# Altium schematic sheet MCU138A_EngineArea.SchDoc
size 431 x 279 mm; Date: Not shown in title block; ApprovedBy: Not shown in title block; CheckedBy: Not shown in title block; Author: Not shown in title block; CompanyName: Not shown in title block; DrawnBy: Jonathan Cohen; Engineer: Not shown in title block; Organization: Not shown in title block; Address1: Not shown in title block; Address2: Not shown in title block; Address3: Not shown in title block; Address4: Not shown in title block; DocumentNumber: 2; Revision: Use project parameter SCH_Rev; SheetNumber: 1; SheetTotal: 2; PageSetup: Record=PageOptions¦CenterHorizontal=True¦CenterVertical=True¦PrintScale=1.00¦XCorrection=1.00¦YCorrection=1.00¦PrintKind=0¦BorderSize=5000000¦LeftOffset=0¦BottomOffset=0¦Orientation=2¦PaperLength=1000¦PaperWidth=1000¦Scale=100¦PaperSource=15¦PrintQuality=600¦MediaType=1¦DitherType=10¦PaperKind=Letter¦PrintScaleMode=1
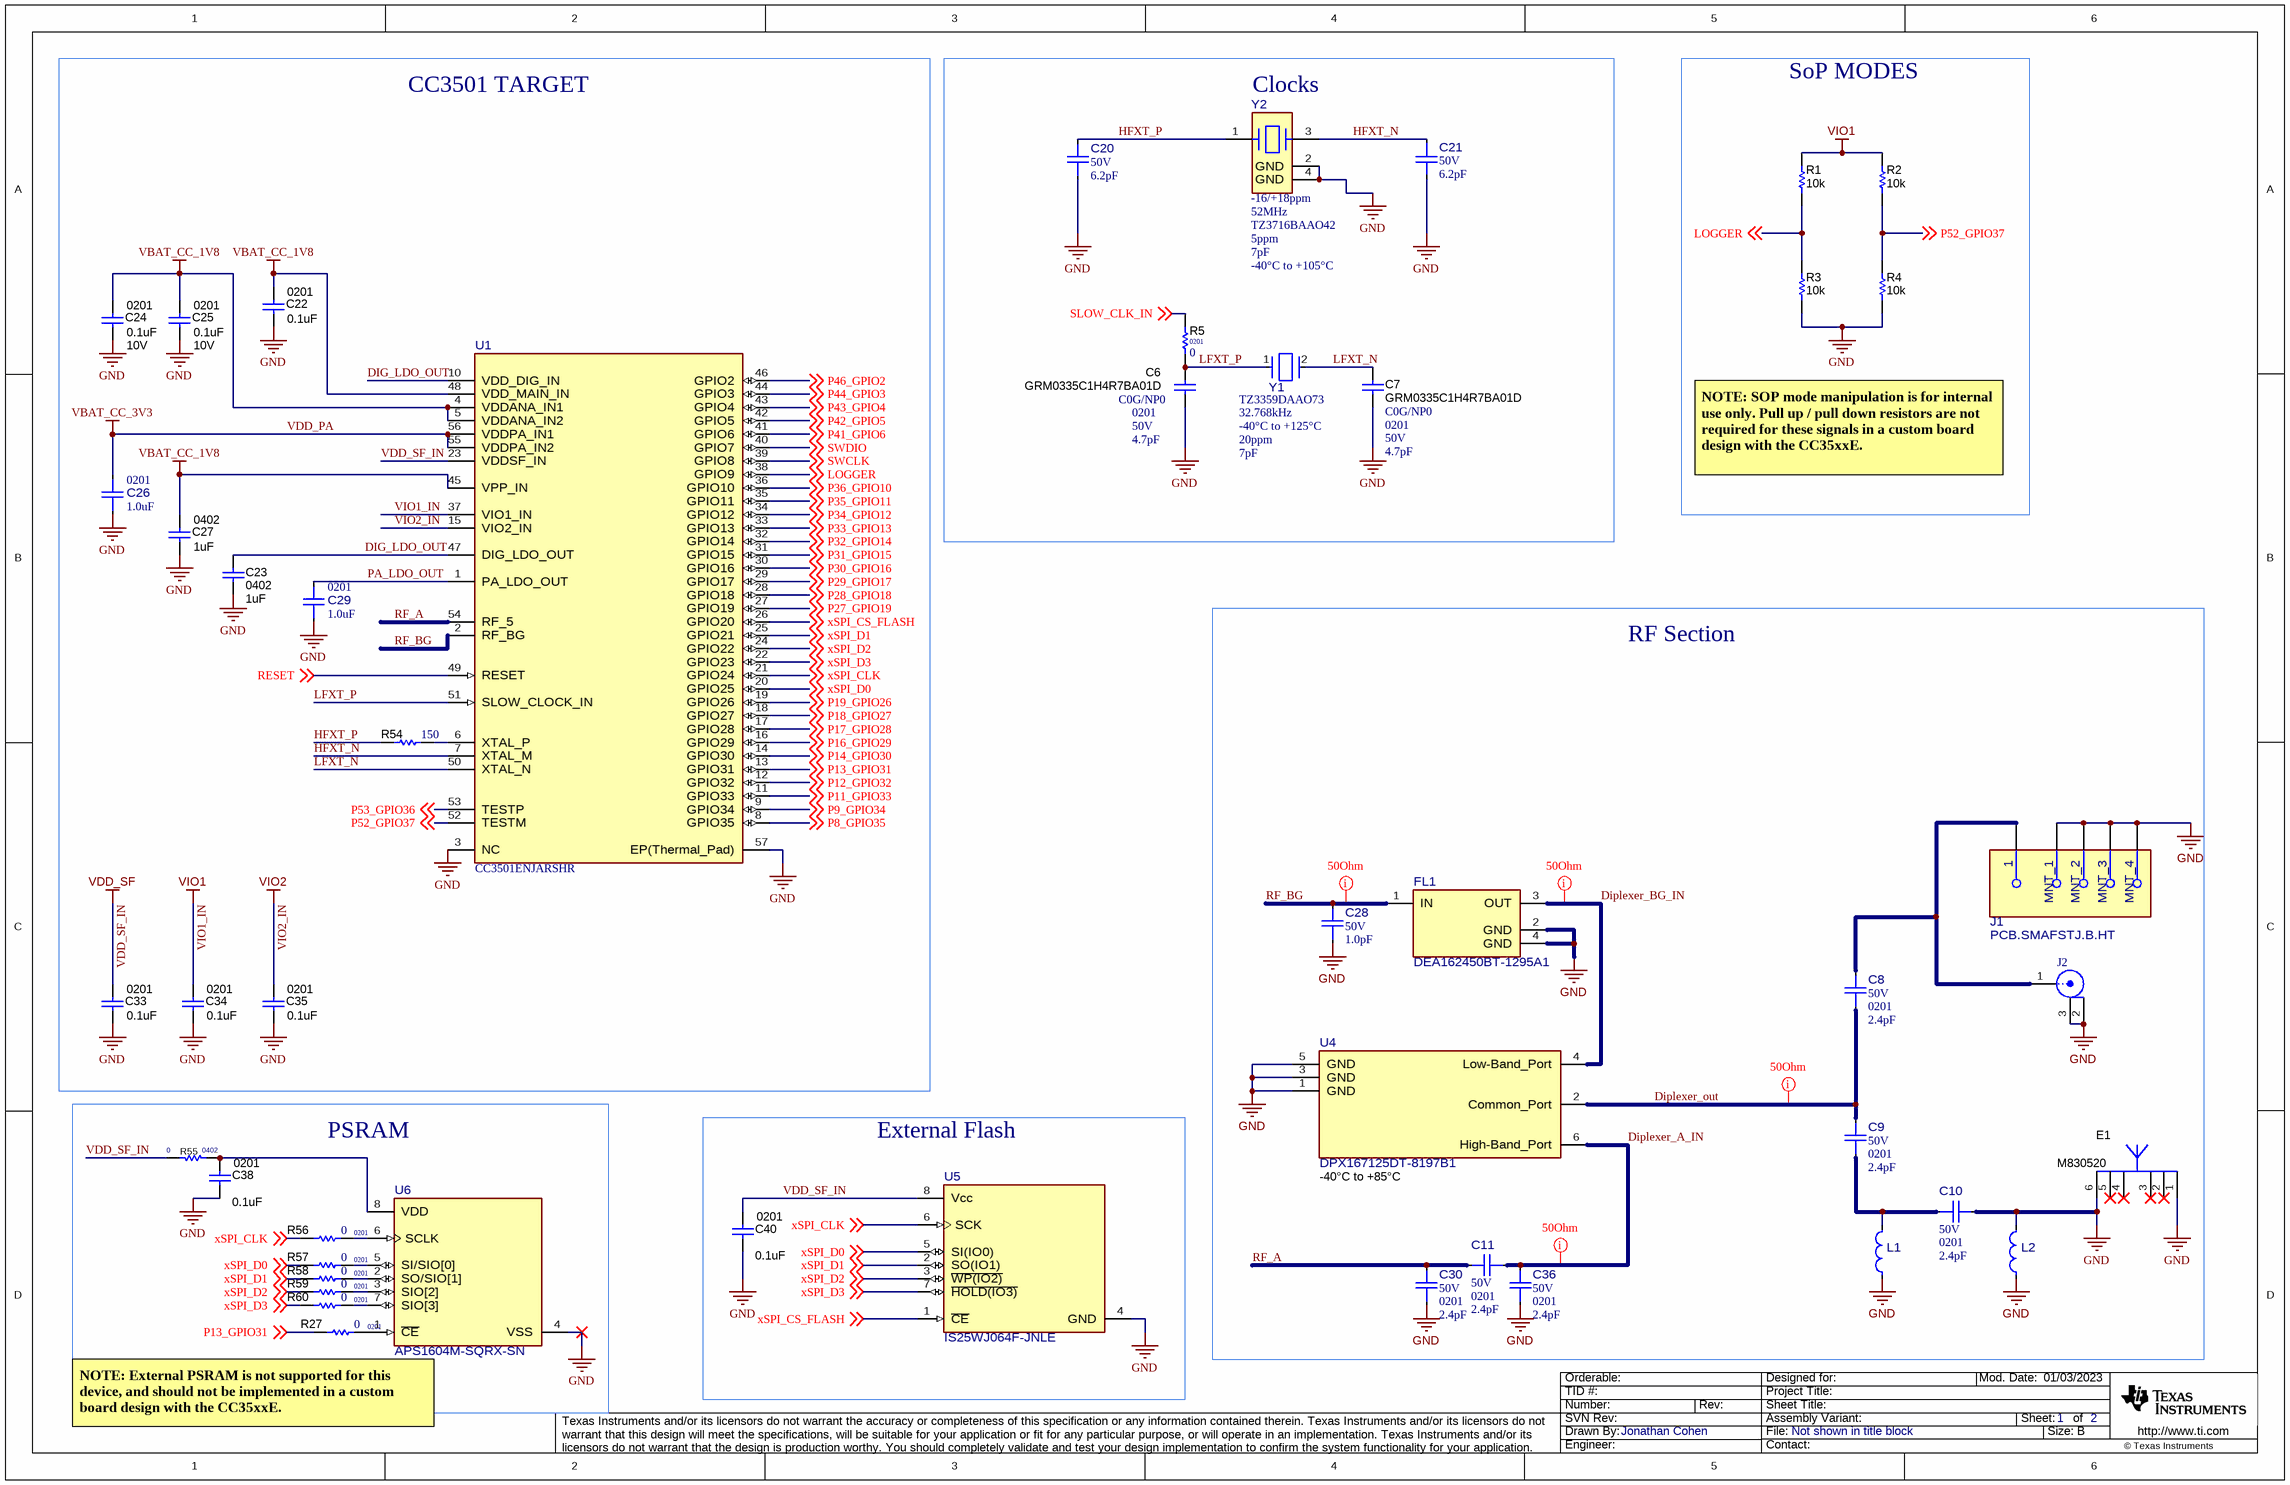
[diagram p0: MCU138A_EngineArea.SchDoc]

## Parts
C6  GRM0335C1H4R7BA01D  TempCo: C0G/NP0  PackageReference: 0201  VDC_V: 50V  ValueDisplayed: 4.7pF  [0201_033]
C7  GRM0335C1H4R7BA01D  TempCo: C0G/NP0  PackageReference: 0201  VDC_V: 50V  ValueDisplayed: 4.7pF  [0201_033]
C8  VDC_V: 50V  PackageReference: 0201  ValueDisplayed: 2.4pF  [FP-GRM0335C1H2R4BA01D_0201-MFG]  (hidden comment: GRM0335C1H2R4BA01D)
C9  VDC_V: 50V  PackageReference: 0201  ValueDisplayed: 2.4pF  [FP-GRM0335C1H2R4BA01D_0201-MFG]  (hidden comment: GRM0335C1H2R4BA01D)
C10  VDC_V: 50V  PackageReference: 0201  ValueDisplayed: 2.4pF  [FP-GRM0335C1H2R4BA01D_0201-MFG]  (hidden comment: GRM0335C1H2R4BA01D)
C11  VDC_V: 50V  PackageReference: 0201  ValueDisplayed: 2.4pF  [FP-GRM0335C1H2R4BA01D_0201-MFG]  (hidden comment: GRM0335C1H2R4BA01D)
C20  VDC_V: 50V  ValueDisplayed: 6.2pF  [FP-GRM0335C1H6R2BA01D_0201-MFG]  (hidden comment: GRM0335C1H6R2BA01D)
C21  VDC_V: 50V  ValueDisplayed: 6.2pF  [FP-GRM0335C1H6R2BA01D_0201-MFG]  (hidden comment: GRM0335C1H6R2BA01D)
C22  ValueDisplayed: 0.1uF  [0201]  (hidden comment: GRM033C71A104KE14D)
C23  ValueDisplayed: 1uF  [0402]  (hidden comment: GRM155R70J105MA12D)
C24  VDC_V: 10V  ValueDisplayed: 0.1uF  [0201]  (hidden comment: GRM033C71A104KE14D)
C25  VDC_V: 10V  ValueDisplayed: 0.1uF  [0201]  (hidden comment: GRM033C71A104KE14D)
C26  ValueDisplayed: 1.0uF  PackageReference: 0201  [FP-GRM033D70J105ME01D_0201-MFG]  (hidden comment: GRM033D70J105ME01D)
C27  ValueDisplayed: 1uF  [0402]  (hidden comment: GRM155R70J105MA12D)
C28  VDC_V: 50V  ValueDisplayed: 1.0pF  [FP-GRM0335C1H1R0CA01D_0201-MFG]  (hidden comment: GRM0335C1H1R0CA01D)
C29  ValueDisplayed: 1.0uF  PackageReference: 0201  [FP-GRM033D70J105ME01D_0201-MFG]  (hidden comment: GRM033D70J105ME01D)
C30  VDC_V: 50V  PackageReference: 0201  ValueDisplayed: 2.4pF  [FP-GRM0335C1H2R4BA01D_0201-MFG]  (hidden comment: GRM0335C1H2R4BA01D)
C33  ValueDisplayed: 0.1uF  [0201]  (hidden comment: GRM033C71A104KE14D)
C34  ValueDisplayed: 0.1uF  [0201]  (hidden comment: GRM033C71A104KE14D)
C35  ValueDisplayed: 0.1uF  [0201]  (hidden comment: GRM033C71A104KE14D)
C36  VDC_V: 50V  PackageReference: 0201  ValueDisplayed: 2.4pF  [FP-GRM0335C1H2R4BA01D_0201-MFG]  (hidden comment: GRM0335C1H2R4BA01D)
C38  ValueDisplayed: 0.1uF  [0201]  (hidden comment: GRM033C71A104KE14D)
C40  ValueDisplayed: 0.1uF  [0201]  (hidden comment: GRM033C71A104KE14D)
E1  M830520  [Ethertronics_M830520]
FL1  DEA162450BT-1295A1  [FP-DEA162450BT-1295A1_SMT_FILTER_1MM60_0MM80-MFG]
J1  PCB.SMAFSTJ.B.HT  [FP-PCB.SMAFSTJ.B.HT_SMT_SMA_JACK-MFG]
J2  U.FL-R-SMT-1(01)  [CONN_UFL-R-SMT-1]  (value not drawn)
L1  LQP03HQ3N9B02D  [FP-LQP03HQ3N9B02D_0201-MFG]  (value not drawn)
L2  LQP03HQ3N9B02D  [FP-LQP03HQ3N9B02D_0201-MFG]  (value not drawn)
R1  ValueDisplayed: 10k  [0402]  (hidden comment: RC0402FR-0710KL)
R2  ValueDisplayed: 10k  [0402]  (hidden comment: RC0402FR-0710KL)
R3  ValueDisplayed: 10k  [0402]  (hidden comment: RC0402FR-0710KL)
R4  ValueDisplayed: 10k  [0402]  (hidden comment: RC0402FR-0710KL)
R5  ValueDisplayed: 0  [0201]  (hidden comment: CRCW02010000Z0ED)
R27  ValueDisplayed: 0  [0201]  (hidden comment: CRCW02010000Z0ED)
R54  ValueDisplayed: 150  [0201]  (hidden comment: RC0201FR-7D150RL)
R55  ValueDisplayed: 0  [0402]  (hidden comment: CRCW04020000Z0ED)
R56  ValueDisplayed: 0  [0201]  (hidden comment: CRCW02010000Z0ED)
R57  ValueDisplayed: 0  [0201]  (hidden comment: CRCW02010000Z0ED)
R58  ValueDisplayed: 0  [0201]  (hidden comment: CRCW02010000Z0ED)
R59  ValueDisplayed: 0  [0201]  (hidden comment: CRCW02010000Z0ED)
R60  ValueDisplayed: 0  [0201]  (hidden comment: CRCW02010000Z0ED)
U1  CC3501ENJARSHR  [RSH0056D-MFG]
U4  DPX167125DT-8197B1  Operating Temperature Range: -40°C to +85°C  [FP-DPX167125DT-8197B1_SMD6-MFG]
U5  IS25WJ064F-JNLE  [FP-IS25WJ032F-JNLE_SOIC8-IPC_C]
U6  APS1604M-SQRX-SN  [FP-APS1604M-SQRX-SN_SOP8-IPC_C]
Y1  Frequency_Fixed: 32.768kHz  Load Capacitance: 7pF  Operating Temperature Range: -40°C to +125°C  Tolerance_%: 20ppm  [FP-TZ3359DAAO73_SMT2_1MM65_1MM05-MFG]  (hidden comment: TZ3359DAAO73)
Y2  Frequency Stability: -16/+18ppm  Frequency_Fixed: 52MHz  Frequency Tolerance: 5ppm  Load Capacitance: 7pF  Operating Temperature Range: -40°C to +105°C  [FP-TZ3716BAAO42_SMT_XTAL_2MM05_1MM65-MFG]  (hidden comment: TZ3716BAAO42)

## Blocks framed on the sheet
CC3501 TARGET: C22-C27 C29 C33-C35 R54 U1
Clocks: C6 C7 C20 C21 R5 Y1 Y2
SoP MODES: R1-R4
RF Section: C8-C11 C28 C30 C36 E1 FL1 J1 J2 L1 L2 U4
PSRAM: C38 R27 R55-R60 U6
External Flash: C40 U5

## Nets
GND: C6.2 C7.2 C10.2 C20.1 C21.2 C22.2 C23.1 C24.2 C25.2 C26.1 C27.2 C28.1 C29.1 C30.1 C33.2 C34.2 C35.2 C36.1 C38.2 C40.2 E1.1(Feed) E1.6 FL1.2(GND) FL1.4(GND) J1.2(MNT_1) J1.3(MNT_2) J1.4(MNT_3) J1.5(MNT_4) J2.2 J2.3 L1.1 L2.1 L2.2 R3.2 R4.2 U1.3(NC) U1.57(EP(Thermal_Pad)) U4.1(GND) U4.3(GND) U4.5(GND) U5.4(GND) U6.4(VSS) Y2.2(GND) Y2.4(GND)
VBAT_CC_1V8: C22.1 C24.1 C25.1 C27.1 U1.4(VDDANA_IN1) U1.5(VDDANA_IN2) U1.45(VPP_IN) U1.48(VDD_MAIN_IN)
VDD_PA: C26.2 U1.55(VDDPA_IN2) U1.56(VDDPA_IN1)  [also labelled VBAT_CC_3V3]
VDD_SF_IN: C33.1 C40.1 R55.2 U1.23(VDDSF_IN) U5.8(Vcc)  [also labelled VDD_SF]
VIO1_IN: C34.1 R1.1 R2.1 U1.37(VIO1_IN)  [also labelled VIO1]
VIO2_IN: C35.1 U1.15(VIO2_IN)  [also labelled VIO2]
DIG_LDO_OUT: C23.2 U1.10(VDD_DIG_IN) U1.47(DIG_LDO_OUT)
Diplexer_A_IN: C11.1 C36.2 U4.6(High-Band_Port)
Diplexer_BG_IN: FL1.3(OUT) U4.4(Low-Band_Port)
Diplexer_out: C8.1 C9.2 U4.2(Common_Port)
HFXT_N: C21.1 U1.7(XTAL_M) Y2.3(2_IN/OUT)
HFXT_P: C20.2 R54.2 Y2.1(1_IN/OUT)
LFXT_N: C7.1 U1.50(XTAL_N) Y1.2
LFXT_P: C6.1 R5.1 U1.51(SLOW_CLOCK_IN) Y1.1
LOGGER: R1.2 R3.1 U1.38(GPIO9) ; off-sheet LOGGER
P8_GPIO35: U1.8(GPIO35) ; off-sheet P8_GPIO35
P9_GPIO34: U1.9(GPIO34) ; off-sheet P9_GPIO34
P11_GPIO33: U1.11(GPIO33) ; off-sheet P11_GPIO33
P12_GPIO32: U1.12(GPIO32) ; off-sheet P12_GPIO32
P13_GPIO31: R27.1 U1.13(GPIO31) ; off-sheet P13_GPIO31
P14_GPIO30: U1.14(GPIO30) ; off-sheet P14_GPIO30
P16_GPIO29: U1.16(GPIO29) ; off-sheet P16_GPIO29
P17_GPIO28: U1.17(GPIO28) ; off-sheet P17_GPIO28
P18_GPIO27: U1.18(GPIO27) ; off-sheet P18_GPIO27
P19_GPIO26: U1.19(GPIO26) ; off-sheet P19_GPIO26
P27_GPIO19: U1.27(GPIO19) ; off-sheet P27_GPIO19
P28_GPIO18: U1.28(GPIO18) ; off-sheet P28_GPIO18
P29_GPIO17: U1.29(GPIO17) ; off-sheet P29_GPIO17
P30_GPIO16: U1.30(GPIO16) ; off-sheet P30_GPIO16
P31_GPIO15: U1.31(GPIO15) ; off-sheet P31_GPIO15
P32_GPIO14: U1.32(GPIO14) ; off-sheet P32_GPIO14
P33_GPIO13: U1.33(GPIO13) ; off-sheet P33_GPIO13
P34_GPIO12: U1.34(GPIO12) ; off-sheet P34_GPIO12
P35_GPIO11: U1.35(GPIO11) ; off-sheet P35_GPIO11
P36_GPIO10: U1.36(GPIO10) ; off-sheet P36_GPIO10
P41_GPIO6: U1.41(GPIO6) ; off-sheet P41_GPIO6
P42_GPIO5: U1.42(GPIO5) ; off-sheet P42_GPIO5
P43_GPIO4: U1.43(GPIO4) ; off-sheet P43_GPIO4
P44_GPIO3: U1.44(GPIO3) ; off-sheet P44_GPIO3
P46_GPIO2: U1.46(GPIO2) ; off-sheet P46_GPIO2
P52_GPIO37: R2.2 R4.1 U1.52(TESTM) ; off-sheet P52_GPIO37
P53_GPIO36: U1.53(TESTP) ; off-sheet P53_GPIO36
PA_LDO_OUT: C29.2 U1.1(PA_LDO_OUT)
RESET: U1.49(RESET) ; off-sheet RESET
RF_A: C11.2 C30.2 U1.54(RF_5)
RF_BG: C28.2 FL1.1(IN) U1.2(RF_BG)
SLOW_CLK_IN: R5.2 ; off-sheet SLOW_CLK_IN
SWCLK: U1.39(GPIO8) ; off-sheet SWCLK
SWDIO: U1.40(GPIO7) ; off-sheet SWDIO
xSPI_CLK: R56.1 U1.21(GPIO24) U5.6(SCK) ; off-sheet xSPI_CLK
xSPI_CS_FLASH: U1.26(GPIO20) U5.1(~{CE}) ; off-sheet xSPI_CS_FLASH
xSPI_D0: R57.1 U1.20(GPIO25) U5.5(SI(IO0)) ; off-sheet xSPI_D0
xSPI_D1: R58.1 U1.25(GPIO21) U5.2(SO(IO1)) ; off-sheet xSPI_D1
xSPI_D2: R59.1 U1.24(GPIO22) U5.3(~{WP(IO2)}) ; off-sheet xSPI_D2
xSPI_D3: R60.1 U1.22(GPIO23) U5.7(~{HOLD(IO3)}) ; off-sheet xSPI_D3
NetC8_2: C8.2 J1.1 J2.1
NetC9_1: C9.1 C10.1 L1.2
NetC38_1: C38.1 R55.1 U6.8(VDD)
NetR27_2: R27.2 U6.1(~{CE})
NetR54_1: R54.1 U1.6(XTAL_P)
NetR56_2: R56.2 U6.6(SCLK)
NetR57_2: R57.2 U6.5(SI/SIO[0])
NetR58_2: R58.2 U6.2(SO/SIO[1])
NetR59_2: R59.2 U6.3(SIO[2])
NetR60_2: R60.2 U6.7(SIO[3])

Not connected (* = marked no-connect by the designer): E1 2(GND)* 3(GND)* 4(Feed)* 5*

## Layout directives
rule Undefined: Diplexer_A_IN, Diplexer_BG_IN, Diplexer_out, RF_BG

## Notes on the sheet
- NOTE: SOP mode manipulation is for internal use only. Pull up / pull down resistors are not required for these signals in a custom board design with the CC35xxE.
- NOTE: External PSRAM is not supported for this device, and should not be implemented in a custom board design with the CC35xxE.

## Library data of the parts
C6 C7 = CMP-0080076-1: CAP, CERM, 4.7 pF, 50 V,+/- 3%, C0G/NP0, 0201; Manufacturer: MuRata; TaMin_C: -55°C; Polarized: N; SizeAreaWB_mm2: 2.08; U/M: EA; Value: 4.7pF; TaMax_C: 125°C; SizeZ_mm: 0.33; SizeX_mm: 0.6; SizeY_mm: 0.3; SizeArea_mm2: 0.18; AEC Category: Q200
C8-C11 C30 C36 = CMP-0091210-1: Chip Multilayer Ceramic Capacitors for General Purpose, 0201, 2.4pF, C0G, 30ppm/°C, 0.1pF, 50V; Manufacturer: Murata; SizeZ_mm: 0.33mm; AEC Qualified: No
C20 C21 = CMP-0096092-1: Chip Multilayer Ceramic Capacitors for General Purpose, 0201, 6.2pF, C0G, 30ppm/°C, 0.1pF, 50V; Manufacturer: Murata; SizeZ_mm: 0.33mm; AEC Qualified: No; Tolerance_%: 1.6%
C22 C33 C34 C38 C40 = CMP-0064969-1: CAP, CERM, 0.1 uF, 10 V,+/- 10%, X7S, 0201; Manufacturer: MuRata; TaMin_C: -55°C; Polarized: N; SizeAreaWB_mm2: 2.08; Value1: Unknown; U/M: EA; Value: 0.1uF; TaMax_C: 125°C; SizeZ_mm: 0.26; SizeX_mm: 0.6; SizeY_mm: 0.3; Value2: 10V; SizeArea_mm2: 0.18; Cap_F: 100nF; AEC Category: Q200
C23 C27 = CMP-0006624-2: CAP, CERM, 1 uF, 6.3 V, +/- 20%, X7R, 0402; Manufacturer: MuRata; TaMin_C: -55°C; Polarized: N; SizeAreaWB_mm2: 3; Value1: Unknown; U/M: EA; Value: 1uF; TaMax_C: 125°C; SizeZ_mm: 0.6; SizeX_mm: 1; SizeY_mm: 0.5; Value2: 6.3V; Cap_F: 1µF; AEC Category: Q200
C24 C25 = CMP-0064969-1: CAP, CERM, 0.1 uF, 10 V,+/- 10%, X7S, 0201; Manufacturer: MuRata; TaMin_C: -55°C; Polarized: N; SizeAreaWB_mm2: 2.08; Value1: Unknown; U/M: EA; Value: 0.1uF; TaMax_C: 125°C; SizeZ_mm: 0.26; SizeX_mm: 0.6; SizeY_mm: 0.3; SizeArea_mm2: 0.18; Cap_F: 100nF; AEC Category: Q200
C26 C29 = CMP-0095016-1: Chip Multilayer Ceramic Capacitors for General Purpose, 0201, 1.0uF, X7T, +22%/-33%, 20%, 6.3V; Manufacturer: Murata; Cap_F: 1µF; AEC Qualified: No; Value: 1µF; SizeZ_mm: 0.39mm
C28 = CMP-0090893-1: Chip Multilayer Ceramic Capacitors for General Purpose, 0201, 1.0pF, C0G, 30ppm/°C, 0.25pF, 50V; Manufacturer: Murata; Value: 1pF; SizeZ_mm: 0.33mm; AEC Qualified: No
C35 = CMP-0064969-1: CAP, CERM, 0.1 uF, 10 V,+/- 10%, X7S, 0201; Manufacturer: MuRata; TaMin_C: -55°C; Polarized: N; SizeAreaWB_mm2: 2.08; Value1: Unknown; U/M: EA; TaMax_C: 125°C; SizeZ_mm: 0.26; SizeX_mm: 0.6; SizeY_mm: 0.3; Value2: 10V; SizeArea_mm2: 0.18; Cap_F: 100nF; AEC Category: Q200
E1 = CMP-0001857-1: WLAN ANTENNA 802.11, SMD; Manufacturer: Ethertronics; Alternate Manufacturer: ----; SizeAreaWB_mm2: 50; SizeArea_mm2: 24; SizeX_mm: 3; SizeY_mm: 8; SizeZ_mm: 1.33
FL1 = CMP-0091509-1: 2.45GHz Center Frequency Band Pass RF Filter (Radio Frequency) 100MHz Bandwidth 1.8dB 0603 (1608 Metric), 3 PC Pad; Manufacturer: TDK; Bandwidth: 2400-2500MHz; AEC Qualified: No; Insertion Loss: 1.95dB; SizeZ_mm: 0.7mm
J1 = CMP-0089646-1: SMA Connector Jack, Female Socket 50Ohm Surface Mount Solder; Manufacturer: Taoglas Limited; SizeZ_mm: 10.7mm; AEC Qualified: No; ContactFinish: Gold; Frequency_Fixed: 0-12.4GHz; Voltage_V: 335V; Conn Orientation: Straight; Shrouded: true; Impedance: 50Ω; Standoff Height: 0.7mm; Dielectric Material: PTFE; Is Female: yes
J2 = CMP-0075320-1: Receptacle, Ultra Miniature Coaxial, Male Pin, 50 ohm, SMT; Manufacturer: Hirose Electric Co. Ltd.; Alternate Manufacturer: ----; CNHeader: False; Gender: Female; ContactFinish: Gold
L1 L2 = CMP-0090712-1: 3.9nH Unshielded Thick Film Inductor 500mA 170mOhm Max 0201 (0603 Metric); Manufacturer: Murata; Tolerance_%: 0.1nH; Test Frequency: 500MHz; Material: Non-Magnetic; TaMin_C: -55°C; SizeZ_mm: 0.42mm; TaMax_C: +125°C; AEC Qualified: No; DCR_ohm: 0.17; Q Factor: 20; Self Resonant Frequency: 7GHz
R1-R4 = CMP-0078669-1: RES, 10.0 k, 1%, 0.063 W, 0402; Manufacturer: Yageo America; Power_W: 63mW; Green_Lifecycle: Active; TempCo: 100 ppm/C; Value_Code: 10k0; Green_REACh: Passed; Value: 10.0k; EIA_Code: E96; SizeX_mm: 1; SizeY_mm: 0.5; SizeZ_mm: 0.6; Value2: 0.063W; AEC Qualified: N; AEC Category: Q200
R5 R27 R56-R60 = CMP-0027008-4: RES, 0, 5%, 0.05 W, 0201; Manufacturer: Vishay-Dale; Power_W: 50mW; TempCo: ppm/C; Value_Code: 0000; Value: 0; EIA_Code: E24; SizeX_mm: 0.6; SizeY_mm: 0.3; SizeZ_mm: 0.26; Value2: 0.05W; SizeArea_mm2: 0.18; AEC Qualified: N; AEC Category: Q200
R54 = CMP-0027960-1: RES, 150, 1%, 0.05 W, 0201; Manufacturer: Yageo America; Power_W: 50mW; TempCo: 200 ppm/C; Value_Code: 150R; U/M: EA; Value: 150; EIA_Code: E96; SizeX_mm: 0.6; SizeY_mm: 0.3; SizeZ_mm: 0.26; Value2: 0.05W; SizeArea_mm2: 0.18; AEC Qualified: N; VDC_V: 25V; AEC Category: Q200
R55 = CMP-0026822-3: RES, 0, 5%, 0.063 W, AEC-Q200 Grade 0, 0402; Manufacturer: Vishay-Dale; Power_W: 63mW; TempCo: 200 ppm/C; Value_Code: 0000; Value: 0; EIA_Code: E24; SizeX_mm: 1; SizeY_mm: 0.5; SizeZ_mm: 0.6; Value2: 0.063W; AEC Qualified: Y; VDC_V: 50V; AEC Category: Q200
U1 = CMP-0121078-1: Manufacturer: Texas Instruments; SizeZ_mm: 1mm; Standoff Height: 0mm
U4 = CMP-0091972-1: Multilayer Diplexer For 2.4-2.5GHz W-LAN & Bluetooth / 5-7GHz W-LAN; Manufacturer: TDK; Insertion Loss: 1dB; SizeZ_mm: 0.7mm; AEC Qualified: No
U5 = CMP-0120365-1: FLASH - NOR Memory IC 64Mbit SPI - Quad I/O, QPI, DTR 133 MHz 6 ns 8-SOP; Manufacturer: ISSI; Part Number: IS25WJ032F-JNLE; SizeZ_mm: 1.75mm; Access Time: 7ns; Frequency_Fixed: 133MHz; Max Supply Voltage: 2V; Memory Size: 32Mbits; Min Supply Voltage: 1.65V; Nominal Supply Current: 1.2-10mA; Standoff Height: 0.1mm
U6 = CMP-0121002-1: DRAM IoT RAM 16Mb QSPI (x1,x4) SDR 144/84MHz, RBX, 1.8V, Ext. Temp., SOP8; Manufacturer: AP Memory; SizeZ_mm: 1.75mm; Access Time: 5.5ns; AEC Qualified: No; Frequency_Fixed: 144MHz; Interface: SPI; Max Supply Voltage: 1.98V; Memory Size: 16Mbits; Memory Type: OTHER; Min Supply Voltage: 1.62V; Nominal Supply Current: 5-7mA; Standoff Height: 0.1mm
Y1 = CMP-0001358-1: Crystal Unit 1.6x1.0 Tuning Fork 32.768KHz; Manufacturer: TAI-SAW Technology; Frequency Stability: 380ppm; SizeZ_mm: 0.5mm; AEC Qualified: No; Esr: 120k
Y2 = CMP-0123571-1: Crystal Unit SMD 2.0x1.6 52.0MHz; Manufacturer: TAI-SAW TECHNOLOGY; SizeZ_mm: 0.5mm; AEC Qualified: No; Esr: 30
